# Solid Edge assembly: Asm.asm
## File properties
Author: CADSoft
Template: Sync Iso Assembly.asm
Last saved by: Cadcim
Revision: 12
Application: Solid Edge
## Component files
casting_new.par
brass_new.par
cap_1224.par
Bolt.par
Nut.par
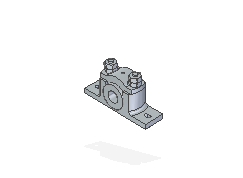
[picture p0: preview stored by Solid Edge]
